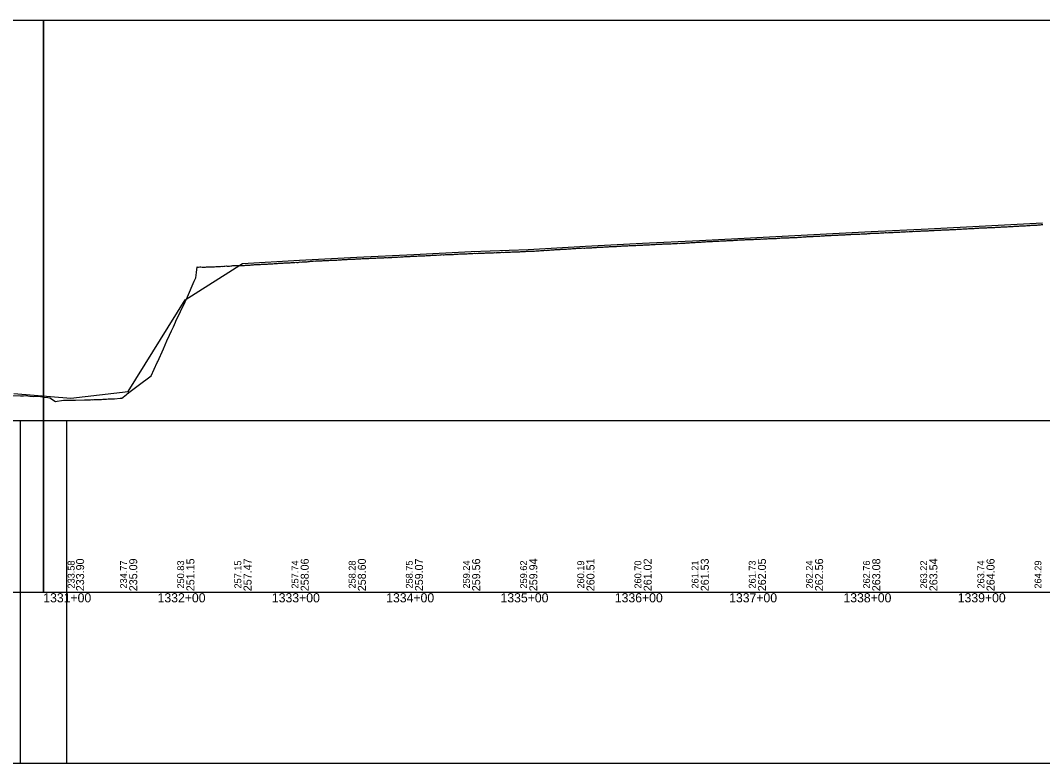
# Model space of a CAD drawing. Extents: x -3627 to 47473, y 2850 to 4350.
# Drawn here: x 20433 to 21327, y 2850 to 3500 of the extents above; entities that cross this region are included whole.
import ezdxf

# ---------------------------------------------------------------- set-up
doc = ezdxf.new("R2010")
doc.units = 0
for name, color, linetype in [('RD_DDB_Profile_EX', 7, 'Continuous'), ('RD_DDB_Profile_PR', 7, 'Continuous'), ('RD_DDB_StaTX', 7, 'Continuous'), ('RD_DDB_StripGrade', 7, 'Continuous'), ('RD_GPK_Profile_Cell', 7, 'Continuous'), ('RD_SHT_ShtClip', 7, 'Continuous')]:
    doc.layers.add(name, color=color, linetype=linetype)

msp = doc.modelspace()

# ---------------------------------------------------------------- linework, layer by layer
at = {"layer": 'RD_DDB_Profile_EX'}
for points in [[(21221.495527, 3315.853), (21222.501838, 3315.898135), (21223.500936, 3315.85864), (21224.494157, 3315.966705), (21225.493305, 3315.876745), (21226.499808, 3315.975845), (21227.499083, 3316.115055), (21228.492472, 3316.12675), (21229.491102, 3316.17033), (21230.497609, 3316.21529), (21231.496893, 3316.229005), (21232.496178, 3316.40657), (21233.489607, 3316.45174), (21234.496296, 3316.462355), (21235.495757, 3316.517645), (21236.495218, 3316.618885), (21237.488763, 3316.57589), (21238.495451, 3316.5827), (21239.494913, 3316.81375), (21240.494375, 3316.765025), (21241.487976, 3316.809865), (21242.494839, 3316.858035), (21243.494478, 3316.871035), (21244.494116, 3316.86787), (21245.487839, 3316.908415), (21246.494695, 3317.048395), (21247.494334, 3317.073785), (21248.493973, 3317.074595), (21249.49367, 3317.125285), (21250.493486, 3317.18967), (21251.493301, 3317.26231), (21252.493116, 3317.352795), (21253.492932, 3317.39938), (21254.493255, 3317.465935), (21255.493068, 3317.40465), (21256.492881, 3317.409115), (21257.492753, 3317.597805), (21258.492745, 3317.68625), (21259.492737, 3317.678615), (21260.492729, 3317.72488), (21261.49222, 3317.825405), (21262.492213, 3317.91774), (21263.492205, 3317.96398), (21264.492198, 3318.010225), (21265.49286, 3318.009985), (21266.49253, 3318.01731), (21267.492701, 3318.07096), (21268.492871, 3318.17071), (21269.493042, 3318.166535), (21270.493832, 3318.258165), (21271.493496, 3318.39978), (21272.493667, 3318.50345), (21273.493898, 3318.507), (21274.494877, 3318.46807), (21275.495231, 3318.52146), (21276.495585, 3318.56278), (21277.488179, 3318.710655), (21278.488533, 3318.71799), (21279.489522, 3318.805055), (21280.48988, 3318.85437), (21281.490298, 3318.865755), (21282.490314, 3318.95224), (21283.490852, 3318.99701), (21284.492048, 3318.962305), (21285.498473, 3318.9594), (21286.499013, 3319.05003), (21287.491788, 3319.159835), (21288.492328, 3319.212945), (21289.493592, 3319.211565), (21290.494324, 3319.2517), (21291.493686, 3319.34303), (21292.493883, 3319.399545), (21293.494611, 3319.44802), (21294.495339, 3319.55929), (21295.489381, 3319.55232), (21296.489447, 3319.61386), (21297.49665, 3319.710545), (21298.496896, 3319.804745), (21299.490587, 3319.809895), (21300.492059, 3319.85833), (21301.4923, 3319.90681), (21302.499076, 3319.95728), (21303.499861, 3320.088515), (21304.493567, 3320.13515), (21305.494419, 3320.14665), (21306.495526, 3320.189935), (21307.495922, 3320.27437), (21308.496252, 3320.32341), (21309.496652, 3320.39796), (21310.497749, 3320.44122), (21311.499436, 3320.475405), (21312.492641, 3320.47626), (21313.49964, 3320.571625), (21314.500789, 3320.628505), (21315.502072, 3320.630405), (21316.49607, 3320.695135), (21317.497362, 3320.878325), (21318.497891, 3320.83557), (21319.505602, 3320.885485), (21320.506882, 3320.97308), (21321.500342, 3320.968435)], [(21321.500342, 3320.968435), (21322.502452, 3321.02047), (21323.501825, 3321.077755), (21324.502605, 3321.17516), (21325.496187, 3321.23001), (21326.496332, 3321.382035), (21327.496333, 3321.4346)], [(21021.545899, 3305.77126), (21022.548457, 3305.858175), (21023.547446, 3305.908605), (21024.550878, 3306.011925), (21025.549907, 3306.00845), (21026.541127, 3305.974035), (21027.544925, 3306.0821), (21028.54301, 3306.169525), (21029.547629, 3306.346), (21030.538804, 3306.398855), (21031.542423, 3306.395285), (21032.540507, 3306.40188), (21033.539627, 3306.52656), (21034.543416, 3306.528545), (21035.534707, 3306.60656), (21036.538512, 3306.71481), (21037.536756, 3306.6969), (21038.535948, 3306.74655), (21039.539758, 3306.79037), (21040.53101, 3306.84251), (21041.534895, 3306.955875), (21042.534031, 3307.050045), (21043.53244, 3307.020845), (21044.537345, 3306.939575), (21045.528718, 3307.09714), (21046.532719, 3307.10957), (21047.531129, 3307.20917), (21048.535144, 3307.322335), (21049.534494, 3307.3215), (21050.53307, 3307.37073), (21051.531646, 3307.425585), (21052.528765, 3307.4796), (21053.527342, 3307.439895), (21054.525919, 3307.578105), (21055.525383, 3307.627045), (21056.529557, 3307.59515), (21057.528892, 3307.77796), (21058.527643, 3307.776835), (21059.526394, 3307.69257), (21060.531621, 3307.74331), (21061.530373, 3307.95849), (21062.529125, 3307.968585), (21063.527877, 3308.017415), (21064.532203, 3308.11859), (21065.53101, 3308.16296), (21066.530651, 3308.162015), (21067.535142, 3308.256865), (21068.534786, 3308.31741), (21069.532785, 3308.31073), (21070.524668, 3308.44996), (21071.529879, 3308.36231), (21072.528802, 3308.361135), (21073.527786, 3308.40402), (21074.527622, 3308.440955), (21075.532266, 3308.597145), (21076.530417, 3308.59584), (21077.530257, 3308.682545), (21078.529351, 3308.692925), (21079.533977, 3308.675125), (21080.532357, 3308.68401), (21081.531514, 3308.87618), (21082.530046, 3308.828785), (21083.528375, 3308.86504), (21084.533183, 3308.93291), (21085.531723, 3309.0678), (21086.530995, 3309.059565), (21087.528781, 3309.20627), (21088.528801, 3309.21009), (21089.533676, 3309.2218), (21090.526099, 3309.23949), (21091.530886, 3309.283755), (21092.528844, 3309.406325), (21093.528297, 3309.333245), (21094.534032, 3309.34506), (21095.526458, 3309.527045), (21096.531444, 3309.526655), (21097.531723, 3309.624295), (21098.528893, 3309.72025), (21099.534807, 3309.775775), (21100.527211, 3309.807875), (21101.532166, 3309.7957), (21102.532353, 3309.805555), (21103.529323, 3309.882315), (21104.528742, 3309.974085), (21105.526745, 3309.990205), (21106.532632, 3310.039945), (21107.532221, 3310.11729), (21108.529385, 3310.163505), (21109.529725, 3310.17326), (21110.534838, 3310.241105), (21111.532974, 3310.268545), (21112.531111, 3310.22043), (21113.529116, 3310.310985), (21114.527428, 3310.46846), (21115.525739, 3310.520025), (21116.524778, 3310.53912), (21117.523083, 3310.623445), (21118.521388, 3310.641945), (21119.524431, 3310.673585), (21120.523442, 3310.80912), (21121.521816, 3310.893185)], [(21121.521816, 3310.893185), (21122.520303, 3310.894295), (21123.519464, 3310.940335), (21124.517108, 3310.986495), (21125.515596, 3311.077205), (21126.514085, 3311.138865), (21127.513226, 3311.20576), (21128.51739, 3311.2685), (21129.515144, 3311.30506), (21130.514441, 3311.29114), (21131.513891, 3311.306535), (21132.511928, 3311.352135), (21133.510592, 3311.538215), (21134.509256, 3311.634205), (21135.508691, 3311.629945), (21136.50735, 3311.680865), (21137.511786, 3311.75312), (21138.510625, 3311.829945), (21139.510214, 3311.83487), (21140.508456, 3311.899245), (21141.507294, 3311.849705), (21142.506133, 3311.89548), (21143.505714, 3312.090995), (21144.50455, 3312.091485), (21145.503446, 3312.155795), (21146.508925, 3312.248695), (21147.515164, 3312.246035), (21148.51418, 3312.291445), (21149.512606, 3312.37726), (21150.512365, 3312.431705), (21151.511381, 3312.45982), (21152.510397, 3312.50989), (21153.509473, 3312.559835), (21154.509415, 3312.55459), (21155.514337, 3312.6473), (21156.513533, 3312.74697), (21157.512728, 3312.75129), (21158.512078, 3312.795785), (21159.511274, 3312.84077), (21160.51047, 3312.926355), (21161.510479, 3312.980225), (21162.50986, 3312.9889), (21163.509241, 3313.042905), (21164.514332, 3313.135175), (21165.514466, 3313.14831), (21166.513089, 3313.14788), (21167.513069, 3313.18311), (21168.511688, 3313.273075), (21169.511734, 3313.39159), (21170.510528, 3313.38592), (21171.509928, 3313.390165), (21172.510102, 3313.353905), (21173.514599, 3313.46014), (21174.514766, 3313.554525), (21175.514164, 3313.699135), (21176.512942, 3313.74347), (21177.513178, 3313.822815), (21178.512753, 3313.83167), (21179.512488, 3313.83511), (21180.51206, 3313.87411), (21181.511631, 3313.978165), (21182.517065, 3313.984055), (21183.51663, 3313.99323), (21184.509222, 3314.004375), (21185.514565, 3314.18056), (21186.507167, 3314.217105), (21187.512796, 3314.24718), (21188.511124, 3314.295805), (21189.511646, 3314.394215), (21190.509355, 3314.44753), (21191.509107, 3314.315435), (21192.508184, 3314.454195), (21193.507401, 3314.497805), (21194.506652, 3314.6507), (21195.505995, 3314.629855), (21196.504506, 3314.62879), (21197.510945, 3314.688365), (21198.503099, 3314.78909), (21199.509538, 3314.848585), (21200.501549, 3314.858885), (21201.507331, 3314.81837), (21202.500242, 3314.818835), (21203.506148, 3315.000915), (21204.49963, 3315.047175), (21205.50554, 3315.06082), (21206.504242, 3315.06348), (21207.504357, 3315.20253), (21208.503063, 3315.25097), (21209.502533, 3315.235565), (21210.501433, 3315.28829), (21211.501712, 3315.344365), (21212.500614, 3315.39693), (21213.500892, 3315.50762), (21214.499796, 3315.55121), (21215.505903, 3315.533445), (21216.498977, 3315.579215), (21217.498492, 3315.65368), (21218.504791, 3315.65738), (21219.503205, 3315.70964), (21220.496439, 3315.805125), (21221.495527, 3315.853)], [(20820.979183, 3295.85784), (20821.977468, 3295.971535), (20822.974851, 3295.921045), (20823.978806, 3295.89724), (20825.203115, 3296.004085), (20825.974723, 3296.05961), (20826.978759, 3296.277765), (20827.976239, 3296.127115), (20828.981195, 3296.16819), (20829.979791, 3296.295335), (20830.977274, 3296.28728), (20831.986844, 3296.329085), (20833.202391, 3296.276055), (20833.983008, 3296.337705), (20834.98806, 3296.459095), (20835.985641, 3296.46549), (20836.983057, 3296.492355), (20837.986191, 3296.543285), (20838.984759, 3296.542435), (20839.982339, 3296.63687), (20841.201666, 3296.617325), (20841.983955, 3296.67976), (20842.981636, 3296.77075), (20843.985861, 3296.78681), (20844.983542, 3296.83146), (20845.981056, 3296.86168), (20846.985282, 3296.85858), (20847.982962, 3296.87659), (20849.200941, 3296.87119), (20849.98377, 3296.89526), (20850.982562, 3296.95927), (20851.981366, 3296.99222), (20852.984672, 3297.0002), (20853.983481, 3297.193765), (20854.980064, 3297.2078), (20855.984393, 3297.1557), (20857.200217, 3297.27041), (20857.98108, 3297.354295), (20858.984294, 3297.397), (20859.982176, 3297.426585), (20860.986609, 3297.444645), (20861.989988, 3297.436375), (20862.982522, 3297.486745), (20863.98573, 3297.519515), (20865.199492, 3297.519935), (20865.987224, 3297.605605), (20866.978798, 3297.655125), (20867.98212, 3297.63948), (20868.986657, 3297.71539), (20869.983737, 3297.74913), (20870.988275, 3297.7831), (20871.979845, 3297.824645), (20873.198767, 3297.90978), (20873.980332, 3297.910865), (20874.984976, 3298.02599), (20875.98962, 3298.064935), (20876.980083, 3298.06453), (20877.984727, 3298.129855), (20878.98191, 3298.22327), (20879.986554, 3298.080635), (20881.198043, 3298.21776), (20881.981745, 3298.29534), (20882.980071, 3298.314945), (20883.983787, 3298.46581), (20884.988539, 3298.548715), (20885.980155, 3298.596235), (20886.983861, 3298.60279), (20887.982197, 3298.670255), (20889.197318, 3298.769995), (20889.976674, 3298.64655), (20890.980326, 3298.756015), (20891.984265, 3298.92017), (20892.981487, 3298.914125), (20893.985151, 3298.925725), (20894.983571, 3298.93456), (20895.980792, 3299.109285), (20897.196594, 3299.291725), (20897.983978, 3299.22847), (20898.981304, 3299.245015), (20899.978631, 3299.253735), (20900.982427, 3299.50617), (20901.980937, 3299.54145), (20902.978264, 3299.59647), (20903.982061, 3299.587545), (20905.195869, 3299.7054), (20905.977984, 3299.80823), (20906.975423, 3299.847285), (20907.980514, 3299.922155), (20908.977953, 3299.999785), (20909.975391, 3300.027345), (20910.980483, 3300.06787), (20911.977922, 3300.11076), (20913.195144, 3300.26817), (20913.972887, 3300.354055), (20914.977144, 3300.363615), (20915.974695, 3300.406285), (20916.977794, 3300.50388), (20917.976501, 3300.5038), (20918.973093, 3300.5575), (20919.970643, 3300.69295), (20921.19442, 3300.759415)], [(20921.19442, 3300.759415), (20921.97253, 3300.83004), (20922.975775, 3300.739195), (20923.974555, 3300.753365), (20924.977806, 3300.961755), (20925.968912, 3300.91401), (20926.973265, 3300.929925), (20927.970931, 3300.97987), (20929.193695, 3301.09284), (20929.972877, 3301.12482), (20930.977344, 3301.154125), (20931.96852, 3301.205745), (20932.966304, 3301.241485), (20933.970762, 3301.50128), (20934.968546, 3301.450815), (20935.971946, 3301.27334), (20937.19297, 3301.47051), (20937.967646, 3301.63316), (20938.965551, 3301.668775), (20939.970124, 3301.713065), (20940.96803, 3301.719), (20941.971563, 3301.700195), (20942.969466, 3301.785735), (20943.967383, 3301.846475), (20945.550808, 3302.02894), (20946.548645, 3301.982025), (20947.552258, 3301.996225), (20948.549869, 3302.186905), (20949.547972, 3302.253235), (20950.544743, 3302.26366), (20951.548382, 3302.27121), (20952.545159, 3302.26256), (20953.549849, 3302.406865), (20954.54199, 3302.408005), (20955.545795, 3302.446315), (20956.542691, 3302.493445), (20957.546513, 3302.644175), (20958.543415, 3302.65346), (20959.542428, 3302.708155), (20960.540245, 3302.76688), (20961.544137, 3302.790985), (20962.540981, 3302.793875), (20963.544988, 3302.96529), (20964.537145, 3302.971855), (20965.540975, 3303.03992), (20966.537995, 3303.086755), (20967.534835, 3303.03987), (20968.539572, 3303.07943), (20969.53101, 3303.101785), (20970.535032, 3303.135835), (20971.532875, 3303.272255), (20972.536234, 3303.32253), (20973.528431, 3303.37299), (20974.533319, 3303.41253), (20975.529631, 3303.420845), (20976.528875, 3303.518645), (20977.533817, 3303.513435), (20978.531695, 3303.65538), (20979.536738, 3303.655225), (20980.535286, 3303.73092), (20981.532604, 3303.838935), (20982.532018, 3303.79145), (20983.536195, 3303.82455), (20984.534912, 3303.94389), (20985.539131, 3303.90508), (20986.538703, 3303.979505), (20987.543182, 3304.089875), (20988.534875, 3304.13988), (20989.534473, 3304.219365), (20990.53876, 3304.27489), (20991.537625, 3304.282885), (20992.542823, 3304.3264), (20993.541556, 3304.41739), (20994.539202, 3304.424845), (20995.538034, 3304.4655), (20996.543385, 3304.51441), (20997.542401, 3304.604075), (20998.54678, 3304.63489), (20999.546574, 3304.63071), (21000.544037, 3304.626665), (21001.54211, 3304.65414), (21002.542073, 3304.6935), (21003.546562, 3304.85525), (21004.546538, 3304.938055), (21005.551005, 3304.93693), (21006.550996, 3304.88264), (21007.547774, 3304.88409), (21008.547774, 3305.052785), (21009.552263, 3305.02853), (21010.552431, 3305.05833), (21011.556993, 3305.23614), (21012.556279, 3305.274185), (21013.554061, 3305.28258), (21014.554258, 3305.30674), (21015.558779, 3305.41263), (21016.549814, 3305.544935), (21017.553324, 3305.5336), (21018.551259, 3305.60654), (21019.555763, 3305.63058), (21020.553697, 3305.681495), (21021.545899, 3305.77126)], [(20621.027549, 3285.55718), (20622.02368, 3285.611425), (20623.025841, 3285.641085), (20624.018396, 3285.671705), (20625.221232, 3285.666655), (20626.022833, 3285.696975), (20627.020461, 3285.75167), (20628.022768, 3285.72448), (20629.019018, 3285.728225), (20630.017656, 3285.948955), (20631.015525, 3286.001845), (20632.017862, 3285.989945), (20633.220507, 3286.01332), (20634.017868, 3286.066545), (20635.015241, 3286.24395), (20636.012898, 3286.2483), (20637.015367, 3286.29918), (20638.017844, 3286.41031), (20639.015501, 3286.465235), (20640.017998, 3286.605845), (20641.219783, 3286.476435), (20642.01309, 3286.447885), (20643.01569, 3286.63811), (20644.012138, 3286.700555), (20645.016037, 3286.77149), (20646.012487, 3286.914225), (20647.016638, 3286.92383), (20648.014349, 3286.93679), (20649.219058, 3286.939265), (20650.013516, 3286.987835), (20651.011299, 3286.98046), (20652.007831, 3287.024965), (20653.0106, 3287.105705), (20654.008608, 3287.17653), (20655.011383, 3287.30495), (20656.007926, 3287.26646), (20657.218333, 3287.35073), (20658.009993, 3287.51804), (20659.006619, 3287.55097), (20660.00468, 3287.583575), (20661.007581, 3287.57369), (20662.004207, 3287.634855), (20663.008542, 3287.739555), (20664.005168, 3287.89107), (20665.217609, 3288.02881), (20666.01146, 3288.115875), (20667.008184, 3288.112795), (20668.004909, 3288.113885), (20669.009332, 3288.117085), (20670.006056, 3288.15022), (20671.00278, 3288.232985), (20672.008373, 3288.22321), (20673.216884, 3288.32703), (20674.008197, 3288.441425), (20675.006408, 3288.38269), (20676.00322, 3288.365355), (20677.000033, 3288.671155), (20678.00351, 3288.73616), (20679.000322, 3288.70136), (20680.002439, 3288.75419), (20681.216159, 3288.89392), (20681.99749, 3288.9814), (20682.999717, 3288.868255), (20683.997959, 3288.909655), (20685.001296, 3289.086315), (20685.998202, 3289.27823), (20686.996424, 3289.41125), (20687.998663, 3289.330645), (20689.215435, 3289.463865), (20690.005617, 3289.622485), (20691.00262, 3289.539475), (20691.999623, 3289.673275), (20693.003279, 3289.674605), (20694.000282, 3289.62472), (20695.002659, 3289.70157), (20696.000938, 3289.759625), (20697.21471, 3289.775025), (20698.001457, 3289.96255), (20698.999824, 3289.94476), (20700.002094, 3289.939035), (20700.999194, 3290.005095), (20701.996087, 3289.979915), (20702.999626, 3290.107555), (20703.997758, 3290.17375), (20705.213985, 3290.355125), (20705.990741, 3290.379955), (20706.99437, 3290.25523), (20707.991368, 3290.255435), (20708.994005, 3290.449065), (20709.991006, 3290.40699), (20710.994647, 3290.50103), (20711.991737, 3290.49229), (20713.213261, 3290.638715), (20713.991493, 3290.67101), (20714.989752, 3290.88318), (20715.992341, 3290.857385), (20716.983062, 3290.85116), (20717.985668, 3290.888405), (20718.983905, 3291.00249), (20719.987639, 3291.10397), (20721.212536, 3291.073675)], [(20721.212536, 3291.073675), (20721.987633, 3291.126395), (20722.984865, 3291.179225), (20723.982081, 3291.307375), (20724.985002, 3291.19371), (20725.982215, 3291.20042), (20726.986058, 3291.372985), (20727.9899, 3291.45997), (20729.211811, 3291.49665), (20729.98458, 3291.500925), (20730.988524, 3291.508845), (20731.985835, 3291.64379), (20732.984245, 3291.664), (20733.980629, 3291.6985), (20734.984574, 3291.685), (20735.982991, 3291.676505), (20737.211087, 3291.7229), (20737.984259, 3291.751485), (20738.988126, 3291.930695), (20739.985525, 3292.029455), (20740.982922, 3292.14865), (20741.986791, 3292.07948), (20742.984185, 3292.156085), (20743.988105, 3292.187375), (20745.210362, 3292.255215), (20745.989439, 3292.29463), (20746.986914, 3292.30045), (20747.985376, 3292.32198), (20748.989524, 3292.34175), (20749.987002, 3292.34768), (20750.991962, 3292.40964), (20751.989433, 3292.53469), (20753.209637, 3292.52067), (20753.990943, 3292.496395), (20754.988504, 3292.571155), (20755.986063, 3292.561475), (20756.990125, 3292.74618), (20757.987679, 3292.752275), (20758.990701, 3292.8445), (20759.988334, 3292.98147), (20761.208913, 3292.973155), (20761.988988, 3292.97143), (20762.993148, 3293.053505), (20763.989849, 3293.09755), (20764.987484, 3293.053285), (20765.991644, 3293.10352), (20766.988348, 3293.289665), (20767.985979, 3293.287385), (20769.208188, 3293.4769), (20769.988126, 3293.665245), (20770.991349, 3293.564685), (20771.990114, 3293.596275), (20772.993323, 3293.59569), (20773.990125, 3293.587395), (20774.98889, 3293.753095), (20775.992094, 3293.70077), (20777.207463, 3293.740355), (20777.987738, 3293.89356), (20778.991028, 3293.94258), (20779.987927, 3293.952115), (20780.991215, 3293.99154), (20781.989173, 3294.019095), (20782.986073, 3294.012475), (20783.988486, 3294.04248), (20785.206739, 3294.163695), (20785.990103, 3294.22865), (20786.987096, 3294.23737), (20787.989634, 3294.31338), (20788.98779, 3294.38012), (20789.983864, 3294.344225), (20790.980856, 3294.425115), (20791.983429, 3294.515225), (20793.206014, 3294.681855), (20793.985144, 3294.74716), (20794.982231, 3294.6194), (20795.979317, 3294.56997), (20796.983099, 3294.77955), (20797.980185, 3294.844425), (20798.982892, 3294.83249), (20799.974324, 3294.96471), (20801.205289, 3295.012885), (20801.975246, 3295.14698), (20802.97807, 3295.106435), (20803.975253, 3295.113445), (20804.979118, 3295.22902), (20805.976301, 3295.215875), (20806.980017, 3295.34236), (20807.9772, 3295.24543), (20809.204565, 3295.24693), (20809.978319, 3295.41465), (20810.975601, 3295.340675), (20811.972882, 3295.347095), (20812.977799, 3295.42765), (20813.975946, 3295.42119), (20814.97985, 3295.592445), (20815.977131, 3295.672225), (20817.20384, 3295.73245), (20817.979406, 3295.76897), (20818.976786, 3295.76847), (20819.974167, 3295.817965), (20820.979183, 3295.85784)], [(20425.239349, 3172.00738), (20433.238624, 3171.777745), (20435.811818, 3171.704325), (20437.750349, 3171.80617), (20439.69978, 3171.659845), (20441.237899, 3171.5009), (20444.804157, 3171.13299), (20446.772975, 3171.278755), (20448.752454, 3171.35534), (20449.237175, 3171.278415), (20453.846021, 3170.54755), (20457.23645, 3170.105775), (20458.91336, 3169.887485), (20463.955629, 3166.69402), (20465.235725, 3166.941125), (20468.953267, 3167.658765), (20470.882909, 3167.8089), (20473.235001, 3167.84865), (20481.234276, 3167.983755), (20489.233551, 3168.118765), (20492.852785, 3168.17981), (20493.650304, 3168.076425), (20494.519895, 3168.10093), (20495.474391, 3168.320435), (20496.268691, 3168.27488), (20497.232827, 3168.34651), (20498.408983, 3168.433805), (20500.751678, 3168.360285), (20501.249424, 3168.393325), (20503.30866, 3168.493785), (20504.093602, 3168.532225), (20505.232102, 3168.64726), (20505.88567, 3168.713215), (20506.954969, 3168.738295), (20508.298886, 3168.79361), (20510.021023, 3168.91802), (20512.333279, 3169.022215), (20513.231377, 3169.06259), (20515.572676, 3169.167895), (20520.496253, 3169.484525), (20521.230653, 3169.537435), (20521.834727, 3169.580875), (20523.003596, 3170.557915), (20524.337334, 3171.54335), (20525.536434, 3172.42313), (20526.621402, 3173.301075), (20529.229928, 3175.30339), (20537.229203, 3181.445675), (20538.397809, 3182.343285), (20545.228479, 3187.447705), (20547.58989, 3189.21294), (20552.894366, 3200.8335), (20553.227754, 3201.59207), (20558.184878, 3212.875045), (20561.227029, 3219.670415), (20563.463154, 3224.667035), (20565.263954, 3228.461735), (20567.068493, 3231.996635), (20568.876782, 3236.17686), (20569.226305, 3236.919945), (20577.22558, 3253.93252), (20579.261824, 3258.264675), (20585.224855, 3271.889865), (20586.581098, 3274.990035), (20587.208028, 3279.537645), (20587.7712, 3284.506825), (20588.425549, 3284.28384), (20589.030291, 3284.28445), (20590.033695, 3284.58468), (20591.029418, 3284.379455), (20592.027788, 3284.320425), (20593.224131, 3284.240625), (20594.027648, 3284.223965), (20595.030073, 3284.212455), (20596.034001, 3284.389925), (20597.025576, 3284.378445), (20598.028003, 3284.378605), (20599.030432, 3284.428765), (20600.030223, 3284.431005), (20601.223406, 3284.51296), (20602.024284, 3284.565615), (20603.026804, 3284.61542), (20604.030807, 3284.665805), (20605.022451, 3284.654065), (20606.026753, 3284.63793), (20607.029271, 3284.722435), (20608.025854, 3284.800885), (20609.222681, 3284.935745), (20610.027513, 3284.852705), (20611.024179, 3285.084865), (20612.028576, 3285.199225), (20613.032666, 3285.26082), (20614.024412, 3285.183475), (20615.027021, 3285.206225), (20616.031112, 3285.20981), (20617.221957, 3285.44463), (20618.030683, 3285.50368), (20619.021866, 3285.525585), (20620.02398, 3285.565975), (20621.027549, 3285.55718)]]:
    msp.add_lwpolyline(points, dxfattribs=at)
at = {"layer": 'RD_DDB_Profile_PR'}
for points in [[(20977.33, 3305.1145), (21027.33, 3307.659), (21077.33, 3310.265), (21127.33, 3312.7935), (21177.33, 3315.4085), (21227.33, 3317.6915), (21277.33, 3320.287), (21327.33, 3323.026)], [(20427.33, 3173.5475), (20477.33, 3169.518), (20527.33, 3175.445), (20577.33, 3255.7545), (20627.33, 3287.3435), (20677.33, 3290.2925), (20727.33, 3293.003), (20777.33, 3295.3645), (20827.33, 3297.8245), (20877.33, 3299.6875), (20927.33, 3302.548), (20977.33, 3305.1145)]]:
    msp.add_lwpolyline(points, dxfattribs=at)
at = {"layer": 'RD_GPK_Profile_Cell'}
msp.add_line((1000, 3000), (46705.077602, 3000), dxfattribs=at)
at = {"layer": 'RD_SHT_ShtClip'}
for points in [[(18953.33, 3500), (18953.33, 3000), (20453.33, 3000), (20453.33, 3000), (20453.33, 3500), (20453.33, 3500)], [(20453.33, 3500), (20453.33, 3000), (21953.33, 3000), (21953.33, 3000), (21953.33, 3500), (21953.33, 3500)], [(18933.33, 3150), (20473.33, 3150), (20473.33, 2850), (18933.33, 2850)], [(20433.33, 3150), (21973.33, 3150), (21973.33, 2850), (20433.33, 2850)]]:
    msp.add_lwpolyline(points, close=True, dxfattribs=at)

# ---------------------------------------------------------------- texts
at = {"layer": 'RD_DDB_StaTX'}
for s, p in [('1331+00', (20453.125471, 2991)), ('1332+00', (20553.125471, 2991)), ('1333+00', (20653.125471, 2991)), ('1334+00', (20753.125471, 2991)), ('1335+00', (20853.125471, 2991)), ('1336+00', (20953.125471, 2991)), ('1337+00', (21053.125471, 2991)), ('1338+00', (21153.125471, 2991)), ('1339+00', (21253.125471, 2991))]:
    msp.add_text(s, height=8, dxfattribs=at).set_placement(p)
at = {"layer": 'RD_DDB_StripGrade'}
for s, height, p in [('233.58', 6, (20480.555832, 3003.073688)), ('233.90', 7, (20488.83, 3000.75)), ('234.77', 6, (20526.33, 3003.073688)), ('235.09', 7, (20535.33, 3000.75)), ('250.83', 6, (20576.33, 3003.073688)), ('251.15', 7, (20585.33, 3000.75)), ('257.15', 6, (20626.33, 3003.073688)), ('257.47', 7, (20635.33, 3000.75)), ('257.74', 6, (20676.33, 3003.073688)), ('258.06', 7, (20685.33, 3000.75)), ('258.28', 6, (20726.33, 3003.073688)), ('258.60', 7, (20735.33, 3000.75)), ('258.75', 6, (20776.33, 3003.073688)), ('259.07', 7, (20785.33, 3000.75)), ('259.24', 6, (20826.33, 3003.073688)), ('259.56', 7, (20835.33, 3000.75)), ('259.62', 6, (20876.33, 3003.073688)), ('259.94', 7, (20885.33, 3000.75)), ('260.19', 6, (20926.33, 3003.073688)), ('260.51', 7, (20935.33, 3000.75)), ('260.70', 6, (20976.33, 3003.073688)), ('261.02', 7, (20985.33, 3000.75)), ('261.21', 6, (21026.33, 3003.073688)), ('261.53', 7, (21035.33, 3000.75)), ('261.73', 6, (21076.33, 3003.073688)), ('262.05', 7, (21085.33, 3000.75)), ('262.24', 6, (21126.33, 3003.073688)), ('262.56', 7, (21135.33, 3000.75)), ('262.76', 6, (21176.33, 3003.073688)), ('263.08', 7, (21185.33, 3000.75)), ('263.22', 6, (21226.33, 3003.073688)), ('263.54', 7, (21235.33, 3000.75)), ('263.74', 6, (21276.33, 3003.073688)), ('264.06', 7, (21285.33, 3000.75)), ('264.29', 6, (21326.33, 3003.073688))]:
    msp.add_text(s, height=height, rotation=90, dxfattribs=at).set_placement(p)

doc.saveas('drawing.dxf')
